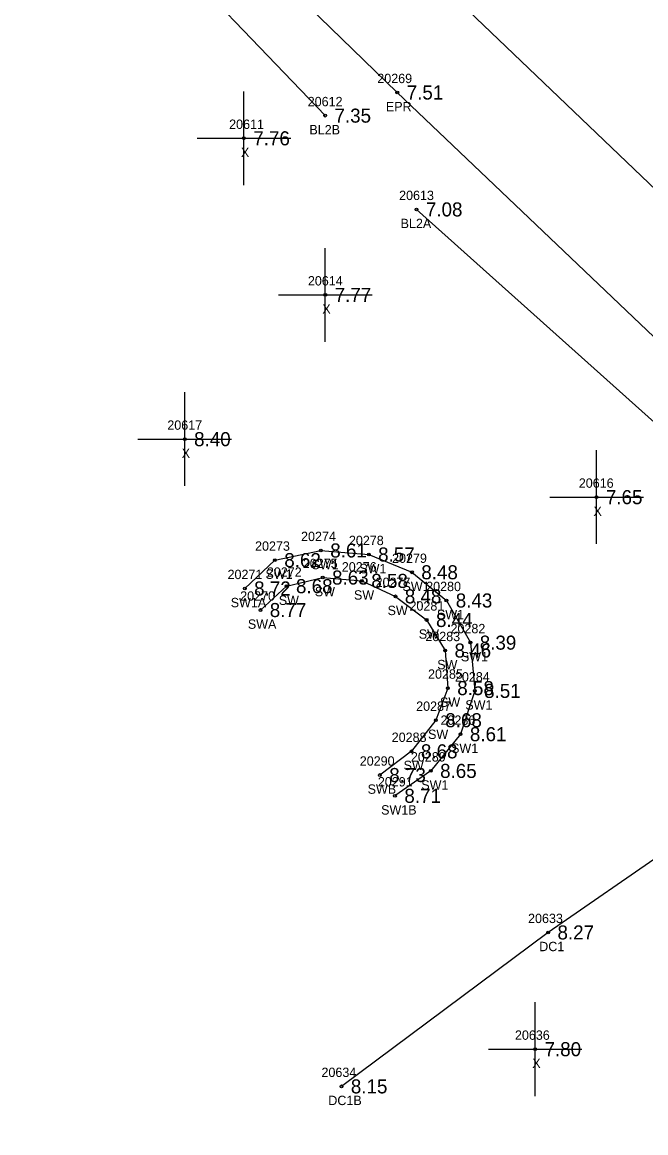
# Model space of a CAD drawing. Extents: x 2608745 to 2610333, y 641917 to 643463.
# Drawn here: x 2609084.1 to 2609150.7, y 642947.8 to 643066.4 of the extents above; entities that cross this region are included whole.
import ezdxf

# ---------------------------------------------------------------- set-up
doc = ezdxf.new("R2010")
doc.units = 0
for name, color, linetype in [('RD_DTM_BkLn1', 7, 'Continuous'), ('RD_DTM_BkLn_txCode', 7, 'Continuous'), ('RD_EX_Conc', 7, 'Continuous'), ('RD_EX_Conc_txCode', 7, 'Continuous'), ('RD_EX_Misc', 7, 'Continuous'), ('RD_EX_Misc_txCode', 7, 'Continuous'), ('RD_EX_Road', 7, 'Continuous'), ('RD_EX_Road_txCode', 7, 'Continuous'), ('RD_EX_TX_Conc_ELEV', 7, 'Continuous'), ('RD_EX_TX_Misc_ELEV', 7, 'Continuous'), ('RD_EX_TX_Road_ELEV', 7, 'Continuous'), ('RD_SMD_Locator', 7, 'Continuous')]:
    doc.layers.add(name, color=color, linetype=linetype)

msp = doc.modelspace()

# ---------------------------------------------------------------- linework, layer by layer
at = {"layer": 'RD_DTM_BkLn1'}
for points in [[(2608814.73, 643373.65), (2608890.45, 643300.26), (2608962.19, 643231.31), (2609034.91, 643161.19), (2609108.48, 643089.9), (2609179.19, 643022.29), (2609255.71, 642948.78), (2609335.19, 642871.73), (2609410.7, 642798.48), (2609491.67, 642719.95), (2609518.07, 642695.15)], [(2609074.55, 643096.96), (2609096.36, 643077.36), (2609116.48, 643056.4)], [(2609126.24, 643046.39), (2609152.99, 643022.42), (2609166.96, 643008.51), (2609173.31, 643002.14), (2609177.12, 643000.67), (2609176.73, 642997.07), (2609173.06, 642994.96), (2609169.97, 642997.99)]]:
    msp.add_lwpolyline(points, dxfattribs=at)
at = {"layer": 'RD_EX_Conc'}
for points in [[(2609107.9, 643005.93), (2609111.12, 643008.96), (2609116.03, 643009.99), (2609121.14, 643009.56), (2609125.75, 643007.66), (2609129.43, 643004.65), (2609131.99, 643000.15), (2609132.46, 642995), (2609130.94, 642990.38), (2609127.76, 642986.46), (2609123.94, 642983.8)], [(2609109.57, 643003.63), (2609112.37, 643006.18), (2609116.22, 643007.1), (2609120.41, 643006.74), (2609123.99, 643005.09), (2609127.32, 643002.57), (2609129.3, 642999.31), (2609129.59, 642995.3), (2609128.31, 642991.87), (2609125.71, 642988.55), (2609122.33, 642986.02)], [(2609183.19, 643002.28), (2609179.86, 642996.96), (2609172.85, 642989.04), (2609168.35, 642985.94), (2609153.06, 642978.04), (2609140.29, 642969.22), (2609118.23, 642952.79)]]:
    msp.add_lwpolyline(points, dxfattribs=at)
at = {"layer": 'RD_EX_Misc'}
for p, q in [((2609107.81, 643048.98), (2609107.81, 643058.98)), ((2609102.81, 643053.98), (2609112.81, 643053.98)), ((2609116.5, 643032.27), (2609116.5, 643042.27)), ((2609111.5, 643037.27), (2609121.5, 643037.27)), ((2609101.49, 643016.87), (2609101.49, 643026.87)), ((2609096.49, 643021.87), (2609106.49, 643021.87)), ((2609145.46, 643010.68), (2609145.46, 643020.68)), ((2609140.46, 643015.68), (2609150.46, 643015.68)), ((2609138.91, 642951.76), (2609138.91, 642961.76)), ((2609133.91, 642956.76), (2609143.91, 642956.76))]:
    msp.add_line(p, q, dxfattribs=at)
at = {"layer": 'RD_EX_Road'}
msp.add_lwpolyline([(2608806.89, 643364.99), (2608810.18, 643361.1), (2608820.75, 643351.25), (2608881.81, 643292.24), (2608917.83, 643257.49), (2608933.21, 643242.71), (2608954.07, 643222.83), (2609026.06, 643154.19), (2609039.6, 643139.96), (2609073.88, 643106.95), (2609100.48, 643081.89), (2609124.19, 643058.87), (2609171.61, 643013.71), (2609183.19, 643002.28), (2609197.91, 642988.37), (2609247.59, 642940.95), (2609328.02, 642863.6), (2609402.61, 642790.3), (2609474.23, 642720.69), (2609483.84, 642711.58), (2609495.78, 642699.92), (2609509.81, 642686.45)], dxfattribs=at)
at = {"layer": 'RD_SMD_Locator'}
for centre in [(2609124.19, 643058.87), (2609116.48, 643056.4), (2609107.81, 643053.98), (2609126.24, 643046.39), (2609116.5, 643037.27), (2609101.49, 643021.87), (2609145.46, 643015.68), (2609116.03, 643009.99), (2609121.14, 643009.56), (2609111.12, 643008.96), (2609125.75, 643007.66), (2609107.9, 643005.93), (2609112.37, 643006.18), (2609116.22, 643007.1), (2609120.41, 643006.74), (2609123.99, 643005.09), (2609109.57, 643003.63), (2609129.43, 643004.65), (2609127.32, 643002.57), (2609131.99, 643000.15), (2609129.3, 642999.31), (2609129.59, 642995.3), (2609132.46, 642995), (2609128.31, 642991.87), (2609130.94, 642990.38), (2609125.71, 642988.55), (2609122.33, 642986.02), (2609127.76, 642986.46), (2609123.94, 642983.8), (2609140.29, 642969.22), (2609138.91, 642956.76), (2609118.23, 642952.79)]:
    msp.add_circle(centre, 0.15, dxfattribs=at)

# ---------------------------------------------------------------- texts
at = {"layer": 'RD_DTM_BkLn_txCode'}
for s, p in [('20612', (2609114.62, 643057.4)), ('BL2B', (2609114.8, 643054.4)), ('20613', (2609124.38, 643047.39)), ('BL2A', (2609124.54, 643044.39))]:
    msp.add_text(s, height=1, dxfattribs=at).set_placement(p)
at = {"layer": 'RD_EX_Conc_txCode'}
for s, p in [('20274', (2609113.91, 643010.99)), ('20273', (2609109, 643009.96)), ('20278', (2609119.02, 643010.56)), ('20279', (2609123.63, 643008.66)), ('20275', (2609114.1, 643008.1)), ('SW1', (2609115.02, 643007.99)), ('20276', (2609118.26, 643007.74)), ('SW1', (2609120.13, 643007.56)), ('20271', (2609106.06, 643006.93)), ('SW1', (2609110.11, 643006.96)), ('20272', (2609110.26, 643007.18)), ('SW', (2609115.38, 643005.1)), ('20277', (2609121.87, 643006.09)), ('SW1', (2609124.74, 643005.66)), ('20280', (2609127.27, 643005.65)), ('SW1A', (2609106.4, 643003.93)), ('20270', (2609107.41, 643004.63)), ('SW', (2609111.53, 643004.18)), ('SW', (2609119.56, 643004.74)), ('SW', (2609123.15, 643003.09)), ('20281', (2609125.49, 643003.57)), ('SWA', (2609108.23, 643001.63)), ('SW1', (2609128.42, 643002.65)), ('SW', (2609126.48, 643000.57)), ('20282', (2609129.87, 643001.15)), ('20283', (2609127.18, 643000.31)), ('SW1', (2609130.98, 642998.15)), ('SW', (2609128.45, 642997.31)), ('20285', (2609127.47, 642996.3)), ('20284', (2609130.34, 642996)), ('SW', (2609128.75, 642993.3)), ('20287', (2609126.2, 642992.87)), ('SW1', (2609131.45, 642993)), ('20286', (2609128.8, 642991.38)), ('SW', (2609127.47, 642989.87)), ('20288', (2609123.59, 642989.55)), ('20289', (2609125.64, 642987.46)), ('SW1', (2609129.93, 642988.38)), ('20290', (2609120.18, 642987.02)), ('SW', (2609124.86, 642986.55)), ('SWB', (2609121.02, 642984.02)), ('20291', (2609122.11, 642984.8)), ('SW1', (2609126.75, 642984.46)), ('SW1B', (2609122.46, 642981.8)), ('20633', (2609138.15, 642970.22)), ('DC1', (2609139.34, 642967.22)), ('20634', (2609116.09, 642953.79)), ('DC1B', (2609116.82, 642950.79))]:
    msp.add_text(s, height=1, dxfattribs=at).set_placement(p)
at = {"layer": 'RD_EX_Misc_txCode'}
for s, p in [('20611', (2609106.23, 643054.98)), ('X', (2609107.49, 643051.98)), ('20614', (2609114.64, 643038.27)), ('X', (2609116.18, 643035.27)), ('20617', (2609099.63, 643022.87)), ('X', (2609101.17, 643019.87)), ('20616', (2609143.57, 643016.68)), ('X', (2609145.14, 643013.68)), ('20636', (2609136.75, 642957.76)), ('X', (2609138.6, 642954.76))]:
    msp.add_text(s, height=1, dxfattribs=at).set_placement(p)
at = {"layer": 'RD_EX_Road_txCode'}
for s, p in [('20269', (2609122.05, 643059.87)), ('EPR', (2609122.97, 643056.87))]:
    msp.add_text(s, height=1, dxfattribs=at).set_placement(p)
at = {"layer": 'RD_EX_TX_Conc_ELEV'}
for s, p in [('8.62', (2609112.12, 643008.21)), ('8.61', (2609117.03, 643009.24)), ('8.57', (2609122.14, 643008.81)), ('8.63', (2609117.22, 643006.35)), ('8.58', (2609121.41, 643005.99)), ('8.48', (2609126.75, 643006.91)), ('8.72', (2609108.9, 643005.18)), ('8.68', (2609113.37, 643005.43)), ('8.48', (2609124.99, 643004.34)), ('8.43', (2609130.43, 643003.9)), ('8.77', (2609110.57, 643002.88)), ('8.44', (2609128.32, 643001.82)), ('8.39', (2609132.99, 642999.4)), ('8.46', (2609130.3, 642998.56)), ('8.58', (2609130.59, 642994.55)), ('8.51', (2609133.46, 642994.25)), ('8.68', (2609129.31, 642991.12)), ('8.61', (2609131.94, 642989.63)), ('8.68', (2609126.71, 642987.8)), ('8.65', (2609128.76, 642985.71)), ('8.73', (2609123.33, 642985.27)), ('8.71', (2609124.94, 642983.05)), ('8.27', (2609141.29, 642968.47)), ('8.15', (2609119.23, 642952.04))]:
    msp.add_text(s, height=1.5, dxfattribs=at).set_placement(p)
at = {"layer": 'RD_EX_TX_Misc_ELEV'}
for s, p in [('7.35', (2609117.48, 643055.65)), ('7.76', (2609108.81, 643053.23)), ('7.08', (2609127.24, 643045.64)), ('7.77', (2609117.5, 643036.52)), ('8.40', (2609102.49, 643021.12)), ('7.65', (2609146.46, 643014.93)), ('7.80', (2609139.91, 642956.01))]:
    msp.add_text(s, height=1.5, dxfattribs=at).set_placement(p)
at = {"layer": 'RD_EX_TX_Road_ELEV'}
msp.add_text('7.51', height=1.5, dxfattribs=at).set_placement((2609125.19, 643058.12))

doc.saveas('drawing.dxf')
